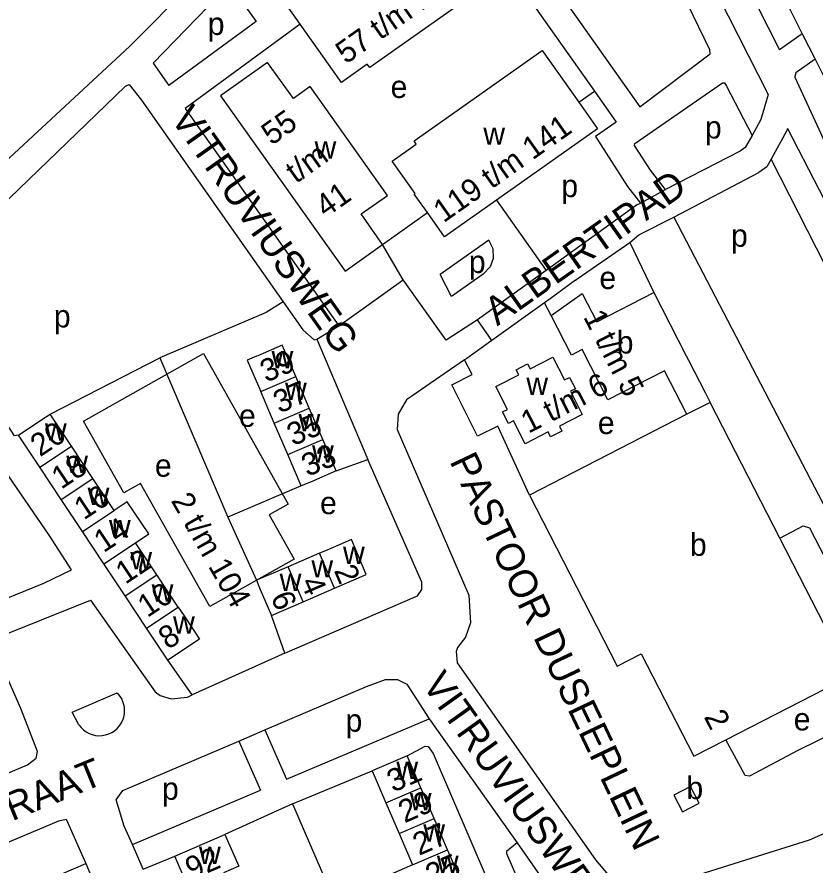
# Model space of a CAD drawing. Extents: x 158848 to 160613, y 385889 to 387762.
# Drawn here: x 159630.1 to 159771.7, y 386409.7 to 386560.1 of the extents above; entities that cross this region are included whole.
import ezdxf

# ---------------------------------------------------------------- set-up
doc = ezdxf.new("R2010")
doc.units = 0
for name, color, linetype in [('BLT_Basislijn', 7, 'Continuous'), ('BLT_Bebouwing', 7, 'Continuous'), ('BLT_Centroide', 7, 'Continuous'), ('BLT_Huisnummer', 7, 'Continuous'), ('BLT_Huisnummer_ tussenligend', 7, 'Continuous'), ('BLT_Huisnummer_reeks', 7, 'Continuous'), ('BLT_Huisnummer_zonder_bebouwing', 7, 'Continuous'), ('BLT_Onderverdeling_panden', 7, 'Continuous'), ('BLT_Plantopo', 7, 'Continuous'), ('BLT_Straatnaam', 7, 'Continuous'), ('BLT_Straatnaam_verkleind', 7, 'Continuous')]:
    doc.layers.add(name, color=color, linetype=linetype)

msp = doc.modelspace()

# ---------------------------------------------------------------- linework, layer by layer
at = {"layer": 'BLT_Basislijn'}
for p, q in [((159702.98, 386597.45), (159740.62, 386544.15)), ((159707.9, 386581.81), (159732.56, 386546.9)), ((159680.36, 386558.82), (159659.94, 386543.87)), ((159769.44, 386557.1), (159765.38, 386554.25)), ((159769.44, 386557.1), (159771.7, 386552.58)), ((159771.7, 386552.58), (159775.9, 386544.2)), ((159729.76, 386544.97), (159732.56, 386546.9)), ((159732.56, 386546.9), (159736.43, 386541.42)), ((159659.94, 386543.87), (159683.08, 386511.16)), ((159766.82, 386540.28), (159811.55, 386453.37)), ((159758.43, 386536.27), (159745.16, 386529.51)), ((159806.71, 386450.8), (159763.9, 386534.88)), ((159746.67, 386524.55), (159761.74, 386532.49)), ((159740.71, 386527.09), (159745.16, 386529.51)), ((159715.19, 386527.59), (159723.99, 386515.13)), ((159740.2, 386526.81), (159723.99, 386515.13)), ((159740.2, 386526.81), (159740.71, 386527.09)), ((159694.97, 386519.75), (159702.91, 386525.38)), ((159713.8, 386520.49), (159705.17, 386514.39)), ((159698.62, 386513.46), (159694.97, 386519.75)), ((159738.83, 386520.06), (159743.09, 386511.24)), ((159723.99, 386515.13), (159711.82, 386506.36)), ((159689.85, 386507.2), (159698.62, 386513.46)), ((159723.7, 386509.38), (159714.38, 386502.68)), ((159724.86, 386507.12), (159723.7, 386509.38)), ((159687.2, 386505.33), (159689.85, 386507.2)), ((159683.32, 386502.93), (159687.2, 386505.33)), ((159714.38, 386502.68), (159711.82, 386506.36)), ((159683.32, 386502.93), (159692.35, 386481.58)), ((159635.96, 386489.65), (159655.43, 386499.62)), ((159655.43, 386499.62), (159667.52, 386471.35)), ((159710.85, 386496.66), (159709.53, 386499.27)), ((159721.02, 386475.28), (159715.42, 386487.5)), ((159686.74, 386479.56), (159692.35, 386481.58)), ((159680.53, 386476.9), (159667.52, 386471.35)), ((159667.52, 386471.35), (159672.57, 386460.16)), ((159677.6, 386447.25), (159675.24, 386453.94)), ((159677.6, 386447.25), (159661.15, 386439.82)), ((159661.15, 386439.82), (159656.86, 386445.97)), ((159677.93, 386424.89), (159703.22, 386435.61)), ((159703.22, 386435.61), (159718.84, 386413.59)), ((159669.48, 386431.65), (159674.08, 386433.62)), ((159674.08, 386433.62), (159677.93, 386424.89)), ((159669.48, 386431.65), (159673.33, 386422.94)), ((159679, 386420.49), (159693.12, 386426.35)), ((159650.57, 386413.29), (159673.33, 386422.94)), ((159679, 386420.49), (159666.99, 386415.09)), ((159679, 386420.49), (159703, 386364.88)), ((159652.47, 386408.91), (159650.57, 386413.29)), ((159652.47, 386408.91), (159658.09, 386411.24)), ((159618.16, 386399.49), (159642.29, 386409.95)), ((159642.29, 386409.95), (159644.32, 386405.2))]:
    msp.add_line(p, q, dxfattribs=at)
for points in [[(159653.96, 386761.48), (159688.89, 386693.23), (159690.55, 386689.53), (159763.39, 386546.32)], [(159660.24, 386760.04), (159732.27, 386620.02), (159733.09, 386617.95), (159765.38, 386554.25)], [(159668.69, 386753.01), (159765.45, 386565.06), (159769.44, 386557.1)], [(159573.48, 386514.55), (159589.7, 386503.28), (159591.03, 386503.75), (159608.94, 386517.82), (159624.63, 386531.34), (159650.13, 386554.93), (159661.12, 386566.05), (159675.68, 386579.96), (159696.76, 386599.11), (159720.05, 386617.5)], [(159740.62, 386544.15), (159753.12, 386553.55), (159753.02, 386554.25), (159749.1, 386562.43), (159722.94, 386612.64), (159721.82, 386612.11), (159715.8, 386607.62), (159702.98, 386597.45)], [(159667.79, 386565.93), (159654.28, 386551.87), (159657.05, 386547.95)], [(159667.79, 386565.93), (159672.53, 386559.29), (159657.05, 386547.95)], [(159771.7, 386552.58), (159768.3, 386550.19), (159768.11, 386549.53), (159768.13, 386549.43)], [(159768.13, 386549.43), (159775.22, 386534.03), (159814.16, 386457.52), (159815.37, 386455.51), (159819.67, 386457.19)], [(159630.33, 386485.91), (159629.62, 386485.81), (159612.22, 386512.57), (159612.29, 386513.11), (159613.3, 386514.39), (159626.94, 386526.22), (159649.36, 386547.83), (159649.99, 386548.11), (159652.21, 386545.34), (159677.32, 386509.58)], [(159745.16, 386529.51), (159742.48, 386532.92), (159739.68, 386537.31), (159739.74, 386537.63), (159755.3, 386548.43), (159755.62, 386548.43), (159756, 386547.79), (159760.52, 386539.09)], [(159763.39, 386546.32), (159762.08, 386541.9), (159760.52, 386539.09)], [(159736.43, 386541.42), (159732.76, 386538.87), (159738.4, 386530.03), (159740.71, 386527.09)], [(159766.82, 386540.28), (159766.72, 386539.95), (159763.9, 386534.88)], [(159760.52, 386539.09), (159759.3, 386536.91), (159758.43, 386536.27)], [(159763.9, 386534.88), (159763.14, 386533.52), (159761.74, 386532.49)], [(159738.83, 386520.06), (159740.41, 386521.42), (159746.67, 386524.55)], [(159746.67, 386524.55), (159789.21, 386442.86)], [(159713.8, 386520.49), (159713.84, 386520.43), (159714.5, 386519.03), (159714.57, 386517.25), (159714.03, 386515.79), (159712.83, 386514.49), (159707.17, 386510.52), (159705.17, 386514.39)], [(159729.2, 386513.42), (159729.68, 386513.77), (159738.83, 386520.06)], [(159711.82, 386506.36), (159706.22, 386502.75), (159698.62, 386513.46)], [(159729.2, 386513.42), (159724.68, 386510.08), (159723.7, 386509.38)], [(159683.08, 386511.16), (159687.2, 386505.33)], [(159677.32, 386509.58), (159674.33, 386507.64), (159655.43, 386499.62)], [(159677.32, 386509.58), (159680.84, 386504.58), (159682.82, 386502.82), (159683.32, 386502.93)], [(159714.38, 386502.68), (159709.89, 386499.52), (159709.53, 386499.27)], [(159709.53, 386499.27), (159699.21, 386492.15), (159697.71, 386489.66), (159697.55, 386486.9), (159710.28, 386457.53), (159710.57, 386452.63), (159709.69, 386450.1), (159708.27, 386448.24), (159708.05, 386447.51), (159708.21, 386445.5), (159732.76, 386410.6), (159736.61, 386406.02), (159740.44, 386404.96), (159741.94, 386405.08), (159770.73, 386414.1), (159794.02, 386424.35)], [(159715.42, 386487.5), (159711.8, 386485.7), (159707.23, 386494.85), (159710.85, 386496.66)], [(159677.6, 386447.25), (159701.15, 386457.43), (159701.94, 386458.55), (159701.94, 386459.85), (159692.35, 386481.58)], [(159635.8, 386468.19), (159627.94, 386479.64), (159618.23, 386475.44), (159618.12, 386475.16), (159626.54, 386456.26), (159634.84, 386459.65), (159639.77, 386462.04), (159635.8, 386468.19)], [(159765.45, 386467.62), (159769.62, 386469.83), (159770.72, 386469.44), (159786.55, 386438.8)], [(159625.41, 386449.52), (159643.13, 386456.61), (159654.63, 386440.39), (159655.51, 386439.74), (159657.46, 386439.11), (159660.35, 386439.44), (159661.15, 386439.82)], [(159611.3, 386418.76), (159631.95, 386427.42), (159633.52, 386428.63), (159633.71, 386429.77), (159630.8, 386437.39), (159625.41, 386449.52)], [(159674.08, 386433.62), (159692.11, 386441.32), (159695.47, 386442.58), (159697.62, 386442.58), (159699.24, 386441.72), (159703.22, 386435.61)], [(159641.07, 386434.5), (159639.89, 386436.77), (159647.86, 386440.21), (159648.7, 386439.08)], [(159641.07, 386434.5), (159641.45, 386434.04), (159641.88, 386433.62), (159642.36, 386433.27), (159642.88, 386432.99), (159643.44, 386432.78), (159644.02, 386432.65), (159644.62, 386432.59), (159645.21, 386432.61), (159645.8, 386432.72), (159646.37, 386432.9), (159646.91, 386433.15), (159647.41, 386433.48), (159647.86, 386433.87), (159648.26, 386434.32), (159648.59, 386434.81), (159648.86, 386435.35), (159649.05, 386435.91), (159649.16, 386436.5), (159649.19, 386437.09), (159649.14, 386437.69), (159649.02, 386438.27), (159648.82, 386438.83), (159648.7, 386439.08)], [(159786.55, 386438.8), (159768.63, 386429.94), (159760.07, 386425.4), (159759.28, 386425.55), (159755.9, 386431.89)], [(159650.57, 386413.29), (159649.09, 386416.52), (159647.71, 386421.23), (159648.87, 386422.85), (159669.48, 386431.65)], [(159699.3, 386429.03), (159702.55, 386430.74), (159703.03, 386430.7), (159703.94, 386429.42), (159727.08, 386375.6), (159727.27, 386375.16)], [(159614.47, 386407.77), (159637.5, 386417.49), (159638.83, 386417.79), (159642.29, 386409.95)], [(159718.84, 386413.59), (159716.96, 386412.03), (159716.96, 386411.71), (159727.59, 386387.25), (159728.35, 386386.15), (159770.38, 386398.36)], [(159718.84, 386413.59), (159723.35, 386407.12), (159728.56, 386401.3), (159730.71, 386399.53), (159732.93, 386398.41), (159737.55, 386396.92), (159744.16, 386396.76), (159763.32, 386402.65), (159766.91, 386402.74), (159767.76, 386402.01), (159770.38, 386398.36)]]:
    msp.add_lwpolyline(points, dxfattribs=at)
at = {"layer": 'BLT_Bebouwing'}
for p, q in [((159680.36, 386558.82), (159677.18, 386563.31)), ((159724.86, 386507.12), (159730.41, 386511.04)), ((159681.96, 386490.72), (159679.57, 386496.29)), ((159675.74, 386488.05), (159673.35, 386493.63)), ((159765.45, 386467.62), (159753.08, 386491.73)), ((159684.35, 386485.14), (159681.96, 386490.72)), ((159639.75, 386483.94), (159635.96, 386489.65)), ((159748.94, 386489.61), (159721.02, 386475.28)), ((159678.14, 386482.48), (159675.74, 386488.05)), ((159634.12, 386480.2), (159630.33, 386485.91)), ((159686.74, 386479.56), (159684.35, 386485.14)), ((159643.54, 386478.24), (159639.75, 386483.94)), ((159680.53, 386476.9), (159678.14, 386482.48)), ((159637.91, 386474.5), (159634.12, 386480.2)), ((159647.33, 386472.53), (159643.54, 386478.24)), ((159641.7, 386468.79), (159637.91, 386474.5)), ((159645.49, 386463.08), (159641.7, 386468.79)), ((159654.91, 386461.12), (159651.12, 386466.83)), ((159683.8, 386464.97), (159678.19, 386462.56)), ((159649.28, 386457.38), (159645.49, 386463.08)), ((159678.19, 386462.56), (159672.57, 386460.16)), ((159658.7, 386455.41), (159654.91, 386461.12)), ((159680.85, 386456.35), (159686.46, 386458.76)), ((159653.07, 386451.67), (159649.28, 386457.38)), ((159675.24, 386453.94), (159680.85, 386456.35)), ((159656.86, 386445.97), (159653.07, 386451.67)), ((159699.3, 386429.03), (159693.12, 386426.35)), ((159701.74, 386423.37), (159699.3, 386429.03)), ((159704.09, 386417.92), (159701.74, 386423.37)), ((159695.56, 386420.69), (159697.9, 386415.25)), ((159706.48, 386412.37), (159704.09, 386417.92)), ((159658.09, 386411.24), (159666.99, 386415.09)), ((159697.9, 386415.25), (159700.3, 386409.7)), ((159708.88, 386406.82), (159706.48, 386412.37)), ((159660.51, 386405.59), (159658.09, 386411.24))]:
    msp.add_line(p, q, dxfattribs=at)
for points in [[(159705.13, 386579.87), (159714.54, 386566.55), (159692.7, 386551.12), (159692.25, 386551.74), (159687.67, 386548.49), (159680.36, 386558.82)], [(159696.66, 386534.51), (159700.93, 386537.54), (159700.54, 386538.09), (159723.26, 386554.16), (159729.76, 386544.97)], [(159694.97, 386519.75), (159691.16, 386525.14), (159695.82, 386528.44), (159682.09, 386547.74), (159679.14, 386545.62), (159674.53, 386552.01), (159674.53, 386552.01), (159666.18, 386546.09)], [(159666.18, 386546.09), (159688.3, 386515.01), (159694.97, 386519.75)], [(159729.76, 386544.97), (159733.1, 386540.25), (159715.19, 386527.59)], [(159702.91, 386525.38), (159700.57, 386528.68), (159700.74, 386528.8), (159696.66, 386534.51)], [(159715.19, 386527.59), (159705.96, 386521.07), (159702.91, 386525.38)], [(159730.41, 386511.04), (159733.01, 386506.02), (159743.09, 386511.24)], [(159743.09, 386511.24), (159748.85, 386500), (159749.25, 386499.19), (159752.2, 386493.45), (159753.08, 386491.73)], [(159748.94, 386489.61), (159744.98, 386497.34), (159734.94, 386492.2), (159730.39, 386501.09), (159728.46, 386500.1), (159724.86, 386507.12)], [(159679.57, 386496.29), (159677.97, 386500), (159677.17, 386501.87), (159672.82, 386500), (159672.58, 386499.9), (159670.96, 386499.2), (159673.35, 386493.63)], [(159630.33, 386485.91), (159634.49, 386488.68), (159635.96, 386489.65)], [(159686.74, 386479.56), (159682.15, 386477.59), (159680.53, 386476.9)], [(159721.02, 386475.28), (159736.6, 386444.91), (159740.87, 386447.1), (159750.18, 386428.95), (159755.9, 386431.89)], [(159651.12, 386466.83), (159653.46, 386468.38), (159649.66, 386474.1), (159647.33, 386472.53)], [(159755.9, 386431.89), (159777.98, 386443.21), (159765.45, 386467.62)], [(159686.46, 386458.76), (159692.08, 386461.17), (159689.42, 386467.38), (159684.82, 386465.41), (159683.8, 386464.97)], [(159672.57, 386460.16), (159673.26, 386458.54), (159675.24, 386453.94)], [(159658.7, 386455.41), (159659.73, 386453.87), (159662.49, 386449.71), (159656.86, 386445.97)], [(159693.12, 386426.35), (159695.56, 386420.69)], [(159751.16, 386420.62), (159749.6, 386423.61), (159746.62, 386422.05), (159748.17, 386419.06), (159751.16, 386420.62)], [(159666.99, 386415.09), (159669.43, 386409.45), (159666.71, 386408.27)], [(159700.3, 386409.7), (159692.45, 386406.24), (159693.75, 386403.23), (159701.62, 386406.63), (159702.69, 386404.15)]]:
    msp.add_lwpolyline(points, dxfattribs=at)
msp.add_lwpolyline([(159715.06, 386494.53), (159719.12, 386496.63), (159718.66, 386497.52), (159720.67, 386498.56), (159721.13, 386497.67), (159725.18, 386499.76), (159727.27, 386495.7), (159728.15, 386496.15), (159729.18, 386494.15), (159728.3, 386493.69), (159730.41, 386489.59), (159726.34, 386487.51), (159726.8, 386486.61), (159724.79, 386485.59), (159724.33, 386486.48), (159720.26, 386484.39), (159718.17, 386488.46), (159717.28, 386488), (159716.25, 386490.02), (159717.14, 386490.47)], close=True, dxfattribs=at)
at = {"layer": 'BLT_Onderverdeling_panden'}
for p, q in [((159673.35, 386493.63), (159679.57, 386496.29)), ((159753.08, 386491.73), (159748.94, 386489.61)), ((159675.74, 386488.05), (159681.96, 386490.72)), ((159678.14, 386482.48), (159684.35, 386485.14)), ((159634.12, 386480.2), (159639.75, 386483.94)), ((159637.91, 386474.5), (159643.54, 386478.24)), ((159641.7, 386468.79), (159647.33, 386472.53)), ((159645.49, 386463.08), (159651.12, 386466.83)), ((159686.46, 386458.76), (159683.8, 386464.97)), ((159680.85, 386456.35), (159678.19, 386462.56)), ((159649.28, 386457.38), (159654.91, 386461.12)), ((159653.07, 386451.67), (159658.7, 386455.41)), ((159695.56, 386420.69), (159701.74, 386423.37)), ((159697.9, 386415.25), (159704.09, 386417.92)), ((159700.3, 386409.7), (159706.48, 386412.37))]:
    msp.add_line(p, q, dxfattribs=at)
at = {"layer": 'BLT_Plantopo'}
msp.add_lwpolyline([(159641.88, 386488.41), (159663.19, 386500.4), (159678.23, 386473.66), (159674.86, 386471.76), (159679.28, 386463.9), (159664.32, 386455.49), (159652.03, 386477.34), (159649.05, 386475.66)], close=True, dxfattribs=at)

# ---------------------------------------------------------------- texts
at = {"layer": 'BLT_Centroide'}
for s, p in [('p', (159663.94, 386556.9)), ('e', (159696.39, 386545.71)), ('p', (159752.16, 386538.53)), ('w', (159712.84, 386537.41)), ('w', (159682.9, 386534.98)), ('p', (159726.68, 386528.14)), ('p', (159756.79, 386519.33)), ('p', (159710.27, 386514.67)), ('e', (159733.44, 386511.83)), ('p', (159636.63, 386505.02)), ('b', (159736.51, 386500.39)), ('w', (159675.26, 386497.75)), ('w', (159677.65, 386492.16)), ('w', (159720.47, 386493.05)), ('e', (159669.49, 386487.38)), ('w', (159680.05, 386486.59)), ('e', (159733.16, 386486.1)), ('w', (159635.05, 386484.92)), ('w', (159682.44, 386481.03)), ('w', (159638.83, 386479.22)), ('e', (159654.56, 386478.53)), ('w', (159642.62, 386473.52)), ('e', (159683.87, 386471.89)), ('w', (159646.41, 386467.8)), ('b', (159749.5, 386464.5)), ('w', (159687.94, 386463.06)), ('w', (159650.2, 386462.11)), ('w', (159682.33, 386460.66)), ('w', (159676.7, 386458.25)), ('w', (159653.98, 386456.39)), ('w', (159657.78, 386450.69)), ('p', (159688.39, 386433.31)), ('e', (159767.92, 386433.53)), ('w', (159697.41, 386424.91)), ('b', (159748.88, 386421.34)), ('p', (159655.82, 386421.22)), ('w', (159699.8, 386419.38)), ('w', (159702.19, 386413.81)), ('w', (159662.38, 386409.81)), ('w', (159704.59, 386408.25))]:
    msp.add_text(s, height=4, dxfattribs=at).set_placement(p)
at = {"layer": 'BLT_Huisnummer'}
for s, rotation, p in [('39', 23.2086, (159674.31, 386495.19)), ('20', 33.5984, (159634.18, 386481.96)), ('33', 23.2212, (159681.65, 386478.48)), ('16', 33.5984, (159641.95, 386470.75)), ('12', 33.5984, (159649.32, 386459.35)), ('2', 293.2164, (159686.28, 386461.91)), ('6', 293.2121, (159675.06, 386457.21)), ('8', 33.5984, (159656.9, 386447.77)), ('31', 23.4424, (159696.84, 386422.48)), ('92', 23.1655, (159661.04, 386406.96)), ('25', 23.4424, (159703.68, 386405.8))]:
    msp.add_text(s, height=4, rotation=rotation, dxfattribs=at).set_placement(p)
at = {"layer": 'BLT_Huisnummer_ tussenligend'}
for s, rotation, p in [('37', 23.2212, (159676.66, 386489.71)), ('35', 23.2212, (159679.08, 386483.93)), ('18', 33.5984, (159637.94, 386476.21)), ('14', 33.5984, (159645.46, 386464.95)), ('4', 293.2164, (159680.33, 386459.84)), ('10', 33.5984, (159653.22, 386453.45)), ('29', 23.4424, (159698.86, 386417.04)), ('27', 23.4424, (159701.42, 386411.26))]:
    msp.add_text(s, height=4, rotation=rotation, dxfattribs=at).set_placement(p)
at = {"layer": 'BLT_Huisnummer_reeks'}
for s, rotation, p in [('1 t/m 5', 297.2216, (159730.51, 386506.9)), ('1 t/m 6', 27.2216, (159720.84, 386486.13)), ('2', 297.1629, (159751.91, 386435.96))]:
    msp.add_text(s, height=4, rotation=rotation, dxfattribs=at).set_placement(p)
at = {"layer": 'BLT_Huisnummer_zonder_bebouwing'}
for s, rotation, p in [('57 t/m 117', 35.2217, (159688.46, 386551.63)), ('55', 35.2217, (159675.28, 386537.2)), ('119 t/m 141', 35.2217, (159705.79, 386523.48)), ('t/m', 35.2217, (159679.59, 386530.46)), ('41', 35.2217, (159684.87, 386524.39)), ('2 t/m 104', 299.5984, (159657.34, 386474.3))]:
    msp.add_text(s, height=4, rotation=rotation, dxfattribs=at).set_placement(p)
at = {"layer": 'BLT_Straatnaam'}
for s, rotation, p in [('PASTOOR DUSEEPLEIN', 295.4515, (159706.79, 386481.3)), ('VITRUVIUSWEG', 305.4721, (159701.85, 386441.67)), ('VAN ZINNICQSTRAAT', 22.2583, (159581.41, 386397.84))]:
    msp.add_text(s, height=5, rotation=rotation, dxfattribs=at).set_placement(p)
at = {"layer": 'BLT_Straatnaam_verkleind'}
for s, rotation, p in [('VITRUVIUSWEG', 305.2186, (159657.2, 386542.09)), ('ALBERTIPAD', 35.2186, (159715.31, 386505.19))]:
    msp.add_text(s, height=5, rotation=rotation, dxfattribs=at).set_placement(p)

doc.saveas('drawing.dxf')
